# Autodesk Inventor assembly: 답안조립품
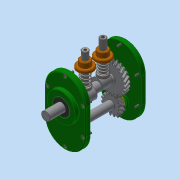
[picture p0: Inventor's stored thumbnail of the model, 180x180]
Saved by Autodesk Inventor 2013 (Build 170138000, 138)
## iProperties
Created: 2018-10
Part Number: 답안조립품
Document SubType Name: Assembly
Designer: Administrator
Mass: 1934.88 g
Surface Area: 2130.53 cm^2
Volume: 748.301 cm^3
Density: 2.5857 g/cm^3
Author: Administrator
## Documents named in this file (15)
- C:\Users\Administrator\Desktop\381007V1020\답안조립품.iam
- C:\Users\Administrator\Desktop\381007V1020\본체.ipt
- C:\Users\Administrator\Desktop\381007V1020\뒤커버.ipt
- C:\Users\Administrator\Desktop\381007V1020\메인축.ipt
- C:\Users\Administrator\Desktop\381007V1020\베어링 608.ipt
- C:\Users\Administrator\Desktop\381007V1020\베어링 6003.ipt
- C:\Users\Administrator\Desktop\381007V1020\볼트 M4.ipt
- C:\Users\Administrator\Desktop\381007V1020\부시.ipt
- C:\Users\Administrator\Desktop\381007V1020\서브축.ipt
- C:\Users\Administrator\Desktop\381007V1020\슬라이더.ipt
- C:\Users\Administrator\Desktop\381007V1020\앞커버.ipt
- C:\Users\Administrator\Desktop\381007V1020\오일실 8 22 7.ipt
- C:\Users\Administrator\Desktop\381007V1020\오일실 17 32 8.ipt
- C:\Users\Administrator\Desktop\381007V1020\가변스프링-1.ipt
- C:\Users\Administrator\Desktop\381007V1020\가변스프링-2.ipt
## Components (2 placed, 2 different names)
1. 가변스프링-1:1
2. 가변스프링-2:1
